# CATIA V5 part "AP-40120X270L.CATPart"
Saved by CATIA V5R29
Part number: AP-40120X270L
Source: Unknown
Bounding box of the stored display mesh (mm): x -135 to 135, y -60 to 60, z -20 to 20
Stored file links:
  C:\가치같이\SmartFactory_BoxErectorConveyor\Boxing(under)\AP-40120X270L.CATPart
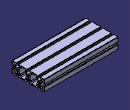
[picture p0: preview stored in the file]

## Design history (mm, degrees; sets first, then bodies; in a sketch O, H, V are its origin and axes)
Body1 (main body)
  Solid1 "PartBody": solid without history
